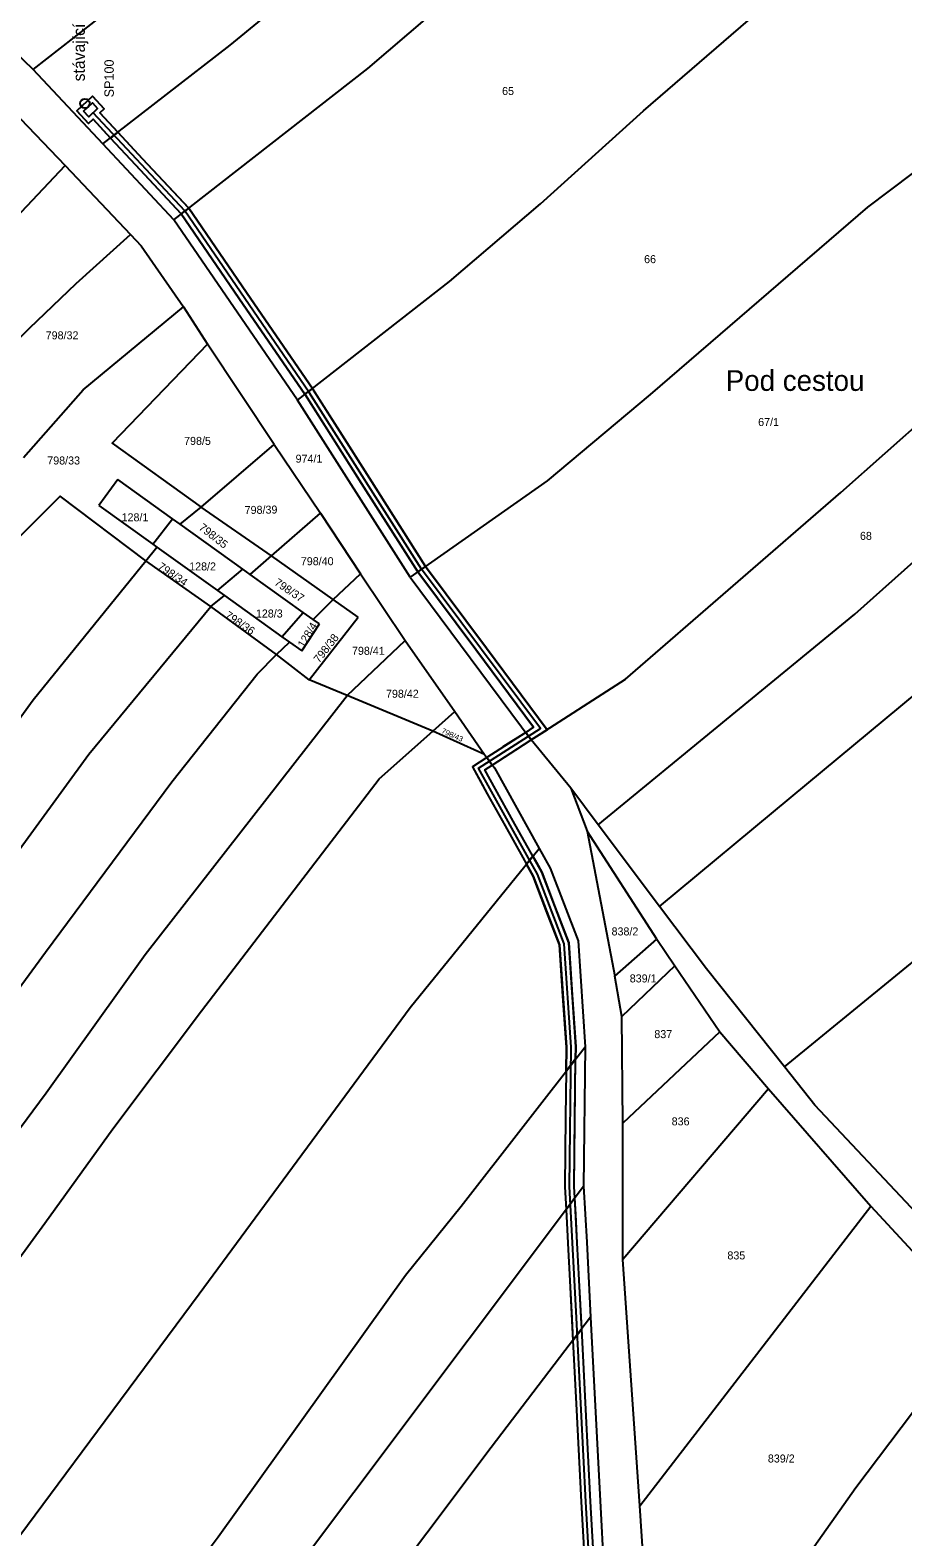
# Model space of a CAD drawing. Extents: x -7483133 to -743907, y -11317770 to -1129777.
# Drawn here: x -747694.4 to -747509.1, y -1131500 to -1131180 of the extents above; entities that cross this region are included whole.
import ezdxf

# ---------------------------------------------------------------- set-up
doc = ezdxf.new("R2010")
doc.units = 0
for name, color, linetype in [('_TRASA_vedení kabelu_CEZ', 7, 'Continuous'), ('Default', 7, 'Continuous'), ('DZ_DO_ostatní', 7, 'Continuous'), ('DZ_DO_ZPF', 7, 'Continuous'), ('Hranice parcel', 7, 'Continuous'), ('hranice VB', 7, 'Continuous'), ('Parcelní čísla', 7, 'Continuous'), ('Pop  PČ popisy', 7, 'Continuous')]:
    doc.layers.add(name, color=color, linetype=linetype)

msp = doc.modelspace()

# ---------------------------------------------------------------- linework, layer by layer
at = {"layer": '_TRASA_vedení kabelu_CEZ'}
msp.add_lwpolyline([(-747683.01, -1131197.18), (-747681.15, -1131195.45), (-747680.03, -1131196.64), (-747681.89, -1131198.38)], close=True, dxfattribs=at)
msp.add_lwpolyline([(-747575.58, -1131507.34), (-747576.38, -1131492.52), (-747578.4, -1131453.5), (-747579.22, -1131437.56), (-747579.88, -1131425.59), (-747579.54, -1131395.96), (-747581.01, -1131374.06), (-747586.67, -1131359.23), (-747588.9, -1131355.23), (-747596.45, -1131341.71), (-747599.17, -1131336.75), (-747586.05, -1131328.3), (-747611.25, -1131294.46), (-747635.1, -1131256.91), (-747661.52, -1131218.38), (-747680.96, -1131197.51)], dxfattribs=at)
at = {"layer": 'Default'}
msp.add_circle((-747682.72, -1131195.55), 1, dxfattribs=at)
msp.add_circle((-747682.72, -1131195.55), 1, dxfattribs=at)
at = {"layer": 'DZ_DO_ostatní'}
msp.add_lwpolyline([(-747587.98, -1131330.73), (-747589.17, -1131329.12), (-747597.45, -1131334.46), (-747596.27, -1131336.08)], close=True, dxfattribs=at)
at = {"layer": 'DZ_DO_ZPF'}
for points in [[(-747681.1, -1131194.04), (-747684.42, -1131197.13), (-747681.94, -1131199.79), (-747681.01, -1131198.92), (-747677.32, -1131202.89), (-747675.73, -1131201.66), (-747679.55, -1131197.56), (-747678.62, -1131196.69)], [(-747675.73, -1131201.66), (-747677.32, -1131202.89), (-747672, -1131208.6), (-747662.31, -1131219), (-747660.71, -1131217.8), (-747660.74, -1131217.75), (-747670.49, -1131207.29)], [(-747660.7, -1131217.79), (-747662.29, -1131219.03), (-747649.12, -1131238.23), (-747636.02, -1131257.33), (-747634.44, -1131256.09), (-747647.5, -1131237.05)], [(-747634.44, -1131256.09), (-747636.02, -1131257.33), (-747624, -1131276.24), (-747612.07, -1131295.03), (-747610.44, -1131293.86), (-747622.34, -1131275.12)], [(-747610.44, -1131293.86), (-747612.07, -1131295.03), (-747599.78, -1131311.53), (-747587.49, -1131328.04), (-747589.17, -1131329.12), (-747587.97, -1131330.74), (-747584.61, -1131328.56), (-747597.51, -1131311.23)], [(-747596.27, -1131336.08), (-747597.45, -1131334.46), (-747600.49, -1131336.42), (-747597.33, -1131342.19), (-747593.55, -1131348.96), (-747589.77, -1131355.72), (-747588.99, -1131357.11), (-747587.64, -1131355.44), (-747591.8, -1131347.98), (-747595.58, -1131341.22), (-747597.84, -1131337.09)], [(-747587.64, -1131355.44), (-747588.99, -1131357.11), (-747587.57, -1131359.66), (-747582, -1131374.28), (-747580.54, -1131395.99), (-747580.6, -1131401.09), (-747578.57, -1131398.49), (-747578.54, -1131395.94), (-747580.03, -1131373.84), (-747585.76, -1131358.81)], [(-747578.57, -1131398.49), (-747580.6, -1131401.09), (-747580.71, -1131410.8), (-747580.88, -1131425.61), (-747580.61, -1131430.49), (-747578.75, -1131428), (-747578.88, -1131425.56)], [(-747578.75, -1131428), (-747580.61, -1131430.49), (-747580.21, -1131437.61), (-747579.8, -1131445.58), (-747579.15, -1131458.26), (-747577.28, -1131455.8), (-747577.81, -1131445.48), (-747578.22, -1131437.51)], [(-747577.28, -1131455.8), (-747579.15, -1131458.26), (-747578.38, -1131473.06), (-747577.37, -1131492.57), (-747576.57, -1131507.4), (-747576.32, -1131512.18), (-747574.45, -1131509.68), (-747574.98, -1131499.88), (-747575.38, -1131492.47), (-747576.39, -1131472.96)]]:
    msp.add_lwpolyline(points, close=True, dxfattribs=at)
at = {"layer": 'Hranice parcel'}
for p, q in [((-747693.71, -1131188.35), (-747705.95, -1131176.64)), ((-747678.94, -1131204.15), (-747693.71, -1131188.35)), ((-747699.59, -1131195.48), (-747686.96, -1131208.76)), ((-747663.87, -1131220.26), (-747678.94, -1131204.15)), ((-747686.96, -1131208.76), (-747673.07, -1131223.37)), ((-747637.6, -1131258.56), (-747663.87, -1131220.26)), ((-747661.79, -1131238.73), (-747656.71, -1131246.65)), ((-747642.55, -1131267.96), (-747656.71, -1131246.65)), ((-747613.72, -1131296.16), (-747637.6, -1131258.56)), ((-747658.09, -1131281.3), (-747642.55, -1131267.96)), ((-747642.55, -1131267.96), (-747632.73, -1131282.6)), ((-747675.77, -1131275.42), (-747679.79, -1131280.94)), ((-747664.12, -1131283.77), (-747675.77, -1131275.42)), ((-747679.79, -1131280.94), (-747668.32, -1131289.17)), ((-747662.52, -1131284.92), (-747658.09, -1131281.3)), ((-747643.16, -1131291.66), (-747658.09, -1131281.3)), ((-747668.32, -1131289.17), (-747664.12, -1131283.77)), ((-747662.52, -1131284.92), (-747664.12, -1131283.77)), ((-747649.2, -1131294.46), (-747662.52, -1131284.92)), ((-747643.16, -1131291.66), (-747632.73, -1131282.6)), ((-747632.73, -1131282.6), (-747624.26, -1131295.45)), ((-747669.82, -1131292.66), (-747667.48, -1131289.77)), ((-747668.32, -1131289.17), (-747667.48, -1131289.77)), ((-747667.48, -1131289.77), (-747654.61, -1131299)), ((-747656, -1131302.39), (-747669.82, -1131292.66)), ((-747654.61, -1131299), (-747649.2, -1131294.46)), ((-747647.65, -1131295.57), (-747649.2, -1131294.46)), ((-747647.65, -1131295.57), (-747643.16, -1131291.66)), ((-747630.05, -1131300.93), (-747643.16, -1131291.66)), ((-747636.4, -1131303.63), (-747647.65, -1131295.57)), ((-747630.05, -1131300.93), (-747624.26, -1131295.45)), ((-747624.26, -1131295.45), (-747614.76, -1131309.6)), ((-747613.72, -1131296.16), (-747587.97, -1131330.74)), ((-747656, -1131302.39), (-747653.1, -1131300.08)), ((-747654.61, -1131299), (-747653.1, -1131300.08)), ((-747653.1, -1131300.08), (-747640.91, -1131308.82)), ((-747634.28, -1131305.15), (-747630.05, -1131300.93)), ((-747624.72, -1131304.69), (-747630.05, -1131300.93)), ((-747642.09, -1131312.59), (-747656, -1131302.39)), ((-747640.91, -1131308.82), (-747636.4, -1131303.63)), ((-747634.28, -1131305.15), (-747636.4, -1131303.63)), ((-747636.7, -1131311.84), (-747632.97, -1131306.09)), ((-747635.14, -1131317.96), (-747624.72, -1131304.69)), ((-747632.97, -1131306.09), (-747634.28, -1131305.15)), ((-747642.09, -1131312.59), (-747639.3, -1131309.98)), ((-747640.91, -1131308.82), (-747639.3, -1131309.98)), ((-747639.3, -1131309.98), (-747636.7, -1131311.84)), ((-747627.04, -1131321.32), (-747614.76, -1131309.6)), ((-747614.76, -1131309.6), (-747604.21, -1131324.68)), ((-747635.14, -1131317.96), (-747642.09, -1131312.59)), ((-747627.04, -1131321.32), (-747635.14, -1131317.96)), ((-747608.88, -1131328.87), (-747627.04, -1131321.32)), ((-747608.88, -1131328.87), (-747604.21, -1131324.68)), ((-747604.21, -1131324.68), (-747597.93, -1131333.8)), ((-747597.93, -1131333.8), (-747608.88, -1131328.87)), ((-747579.59, -1131341), (-747587.97, -1131330.74)), ((-747573.75, -1131348.78), (-747579.59, -1131341)), ((-747579.59, -1131341), (-747576.14, -1131350.08)), ((-747560.74, -1131366.12), (-747573.75, -1131348.78)), ((-747576.14, -1131350.08), (-747570.26, -1131380.88)), ((-747561.31, -1131373.03), (-747576.14, -1131350.08)), ((-747570.26, -1131380.88), (-747561.31, -1131373.03)), ((-747561.31, -1131373.03), (-747557.5, -1131378.68)), ((-747568.77, -1131389.44), (-747570.26, -1131380.88)), ((-747557.5, -1131378.68), (-747568.77, -1131389.44)), ((-747557.5, -1131378.68), (-747547.95, -1131392.74)), ((-747568.57, -1131412.15), (-747568.77, -1131389.44)), ((-747547.95, -1131392.74), (-747568.57, -1131412.15)), ((-747547.95, -1131392.74), (-747537.66, -1131404.8)), ((-747576.54, -1131395.88), (-747576.88, -1131425.52)), ((-747537.66, -1131404.8), (-747568.52, -1131441.05)), ((-747537.66, -1131404.8), (-747515.93, -1131429.75)), ((-747568.52, -1131441.05), (-747568.57, -1131412.15)), ((-747564.97, -1131493.37), (-747515.93, -1131429.75)), ((-747515.93, -1131429.75), (-747492.83, -1131454.72)), ((-747564.97, -1131493.37), (-747568.52, -1131441.05))]:
    msp.add_line(p, q, dxfattribs=at)
for points in [[(-747693.71, -1131188.35), (-747673.39, -1131172.41), (-747656.27, -1131158.12), (-747617.7, -1131124.35), (-747583.1, -1131094.79)], [(-747678.94, -1131204.15), (-747651.91, -1131183.16), (-747620.97, -1131157.74), (-747567.13, -1131110.4)], [(-747663.87, -1131220.26), (-747622.68, -1131188.16), (-747577.82, -1131149.69), (-747551.23, -1131125.94)], [(-747637.6, -1131258.56), (-747605.36, -1131233.4), (-747586.04, -1131216.89), (-747564.17, -1131197.09), (-747518.15, -1131157.34)], [(-747478.68, -1131189), (-747516.61, -1131217.55), (-747562.75, -1131257.36), (-747584.62, -1131275.69), (-747613.72, -1131296.16)], [(-747719.59, -1131243.31), (-747710.17, -1131233.27), (-747686.96, -1131208.76)], [(-747587.97, -1131330.74), (-747567.99, -1131317.8), (-747522.26, -1131278.21), (-747503.48, -1131261.46), (-747452.5, -1131218.84)], [(-747705.1, -1131253.98), (-747694.48, -1131243.3), (-747684.57, -1131233.76), (-747673.07, -1131223.37)], [(-747673.07, -1131223.37), (-747670.79, -1131225.76), (-747661.79, -1131238.73)], [(-747695.74, -1131270.78), (-747683.08, -1131256.39), (-747661.79, -1131238.73)], [(-747573.75, -1131348.78), (-747519.29, -1131304), (-747475.75, -1131265.13), (-747451.48, -1131246.17), (-747439.12, -1131238.12)], [(-747656.71, -1131246.65), (-747676.97, -1131267.67), (-747658.09, -1131281.3)], [(-747560.74, -1131366.12), (-747532.83, -1131342.86), (-747438.82, -1131264.87), (-747425.11, -1131256.95)], [(-747669.82, -1131292.66), (-747687.96, -1131278.99), (-747702.43, -1131293.35), (-747710.63, -1131287.46)], [(-747915.42, -1131619.45), (-747873.23, -1131566.86), (-747843.82, -1131525.97), (-747806.53, -1131475.44), (-747778.43, -1131437.61), (-747729.49, -1131371.5), (-747693.71, -1131322.2), (-747669.82, -1131292.66)], [(-747534.26, -1131400.17), (-747480.38, -1131356.14), (-747430.3, -1131312.29), (-747401.97, -1131292.55)], [(-747895.76, -1131621.42), (-747861.58, -1131578.6), (-747835.67, -1131543.4), (-747806.42, -1131503.18), (-747795.07, -1131488.14), (-747755.24, -1131433.32), (-747715.49, -1131379.82), (-747681.87, -1131333.76), (-747656, -1131302.39)], [(-747879, -1131625.66), (-747851.66, -1131591.69), (-747829.65, -1131563.42), (-747808.64, -1131535.34), (-747757.65, -1131465.52), (-747713.97, -1131406.96), (-747691.09, -1131375.78), (-747664.28, -1131339.63), (-747646.2, -1131316.75), (-747642.09, -1131312.59)], [(-747860.06, -1131629.88), (-747832.75, -1131596.26), (-747816.97, -1131575.83), (-747776.82, -1131523.47), (-747762.78, -1131503.59), (-747734.31, -1131465.05), (-747710.2, -1131431.58), (-747690.98, -1131405.7), (-747669.96, -1131376.28), (-747627.04, -1131321.32)], [(-747842.01, -1131634.16), (-747811.79, -1131593.14), (-747801.87, -1131584.09), (-747752.07, -1131516.87), (-747707.12, -1131455.02), (-747691.23, -1131433.37), (-747676.82, -1131413.33), (-747658, -1131388.25), (-747620.26, -1131339), (-747608.88, -1131328.87)], [(-747597.93, -1131333.8), (-747595.82, -1131336.69), (-747586.28, -1131353.77)], [(-747806.67, -1131645.86), (-747760.08, -1131583.56), (-747741.05, -1131557.9), (-747711.67, -1131520.04), (-747658.45, -1131448.35), (-747613.7, -1131387.55), (-747586.28, -1131353.77)], [(-747586.28, -1131353.77), (-747583.94, -1131357.96), (-747578.05, -1131373.41), (-747576.54, -1131395.88)], [(-747534.26, -1131400.17), (-747550.8, -1131379.36), (-747560.74, -1131366.12)], [(-747772.35, -1131654.05), (-747742.69, -1131616.2), (-747708.15, -1131571.7), (-747696.05, -1131555.49), (-747654.43, -1131499.96), (-747614.66, -1131444.39), (-747602.9, -1131429.72), (-747576.54, -1131395.88)], [(-747506.23, -1131431.25), (-747527.79, -1131408.31), (-747534.26, -1131400.17)], [(-747751.97, -1131658.69), (-747725.51, -1131622.95), (-747709.1, -1131600.51), (-747691.54, -1131577.63), (-747669.23, -1131548.64), (-747625.65, -1131490.48), (-747576.88, -1131425.52)], [(-747576.88, -1131425.52), (-747576.22, -1131437.4), (-747575.4, -1131453.35)], [(-747575.4, -1131453.35), (-747596.53, -1131480.99), (-747637.49, -1131535.62), (-747681.61, -1131594.97), (-747707.2, -1131626.86), (-747733.77, -1131662.83)], [(-747575.4, -1131453.35), (-747573.38, -1131492.36), (-747572.58, -1131507.18)], [(-747559.72, -1131546.32), (-747549.84, -1131533.09), (-747519.12, -1131489.53), (-747492.83, -1131454.72)], [(-747559.72, -1131546.32), (-747562.72, -1131526.64), (-747564.97, -1131493.37)]]:
    msp.add_lwpolyline(points, dxfattribs=at)
at = {"layer": 'hranice VB'}
for p, q in [((-747672, -1131208.6), (-747677.3, -1131202.91)), ((-747662.29, -1131219.03), (-747672, -1131208.6)), ((-747660.71, -1131217.8), (-747662.29, -1131219.03)), ((-747660.71, -1131217.8), (-747647.5, -1131237.05)), ((-747649.12, -1131238.23), (-747662.29, -1131219.03)), ((-747647.5, -1131237.05), (-747634.44, -1131256.09)), ((-747636.02, -1131257.33), (-747649.12, -1131238.23)), ((-747634.44, -1131256.09), (-747636.02, -1131257.33)), ((-747622.34, -1131275.12), (-747610.44, -1131293.86)), ((-747612.08, -1131295.01), (-747624, -1131276.24)), ((-747610.44, -1131293.86), (-747612.08, -1131295.01)), ((-747587.49, -1131328.04), (-747599.78, -1131311.53)), ((-747597.51, -1131311.23), (-747584.61, -1131328.56)), ((-747589.17, -1131329.12), (-747593.99, -1131332.23)), ((-747589.17, -1131329.12), (-747587.49, -1131328.04)), ((-747587.98, -1131330.73), (-747589.17, -1131329.12)), ((-747584.61, -1131328.56), (-747587.98, -1131330.73)), ((-747593.99, -1131332.23), (-747597.45, -1131334.46)), ((-747596.27, -1131336.08), (-747591.23, -1131332.83)), ((-747591.23, -1131332.83), (-747587.98, -1131330.73)), ((-747597.45, -1131334.46), (-747600.49, -1131336.42)), ((-747597.84, -1131337.09), (-747596.27, -1131336.08)), ((-747597.45, -1131334.46), (-747596.27, -1131336.08)), ((-747600.49, -1131336.42), (-747598.91, -1131339.3)), ((-747598.91, -1131339.3), (-747597.33, -1131342.19)), ((-747595.58, -1131341.22), (-747597.84, -1131337.09)), ((-747597.33, -1131342.19), (-747593.55, -1131348.96)), ((-747591.8, -1131347.98), (-747595.58, -1131341.22)), ((-747593.55, -1131348.96), (-747589.77, -1131355.72)), ((-747587.64, -1131355.44), (-747591.8, -1131347.98)), ((-747588.99, -1131357.11), (-747587.64, -1131355.44)), ((-747587.64, -1131355.44), (-747586.89, -1131356.78)), ((-747589.77, -1131355.72), (-747588.99, -1131357.11)), ((-747587.57, -1131359.66), (-747588.99, -1131357.11)), ((-747586.89, -1131356.78), (-747585.76, -1131358.81)), ((-747584.79, -1131366.97), (-747587.57, -1131359.66)), ((-747585.76, -1131358.81), (-747582.89, -1131366.33)), ((-747582, -1131374.28), (-747584.79, -1131366.97)), ((-747582.89, -1131366.33), (-747580.03, -1131373.84)), ((-747581.27, -1131385.13), (-747582, -1131374.28)), ((-747580.03, -1131373.84), (-747579.28, -1131384.89)), ((-747580.54, -1131395.99), (-747581.27, -1131385.13)), ((-747579.28, -1131384.89), (-747578.54, -1131395.94)), ((-747580.6, -1131401.09), (-747580.54, -1131395.99)), ((-747578.54, -1131395.94), (-747578.57, -1131398.49)), ((-747578.57, -1131398.49), (-747580.6, -1131401.09)), ((-747578.71, -1131410.75), (-747578.57, -1131398.49)), ((-747580.6, -1131401.09), (-747580.71, -1131410.8)), ((-747580.71, -1131410.8), (-747580.88, -1131425.61)), ((-747578.88, -1131425.56), (-747578.71, -1131410.75)), ((-747580.88, -1131425.61), (-747580.61, -1131430.49)), ((-747578.75, -1131428), (-747578.88, -1131425.56)), ((-747580.61, -1131430.49), (-747578.75, -1131428)), ((-747578.55, -1131431.54), (-747578.75, -1131428)), ((-747580.61, -1131430.49), (-747580.21, -1131437.61)), ((-747578.22, -1131437.51), (-747578.55, -1131431.54)), ((-747580.21, -1131437.61), (-747579.8, -1131445.58)), ((-747577.81, -1131445.48), (-747578.22, -1131437.51)), ((-747579.8, -1131445.58), (-747579.39, -1131453.56)), ((-747577.4, -1131453.45), (-747577.81, -1131445.48)), ((-747579.39, -1131453.56), (-747579.15, -1131458.26)), ((-747577.28, -1131455.8), (-747577.4, -1131453.45)), ((-747579.15, -1131458.26), (-747577.28, -1131455.8)), ((-747576.39, -1131472.96), (-747577.28, -1131455.8)), ((-747579.15, -1131458.26), (-747578.38, -1131473.06)), ((-747578.38, -1131473.06), (-747577.37, -1131492.57)), ((-747575.38, -1131492.47), (-747576.39, -1131472.96)), ((-747577.37, -1131492.57), (-747576.97, -1131499.98)), ((-747574.98, -1131499.88), (-747575.38, -1131492.47)), ((-747574.58, -1131507.29), (-747574.98, -1131499.88))]:
    msp.add_line(p, q, dxfattribs=at)
for points in [[(-747677.32, -1131202.89), (-747681.01, -1131198.92), (-747681.94, -1131199.79), (-747684.42, -1131197.13), (-747681.1, -1131194.04), (-747678.62, -1131196.69), (-747679.55, -1131197.56), (-747675.73, -1131201.66), (-747677.3, -1131202.91)], [(-747675.73, -1131201.66), (-747670.49, -1131207.29), (-747662.78, -1131215.56), (-747660.74, -1131217.75), (-747660.71, -1131217.8)], [(-747634.44, -1131256.09), (-747634.26, -1131256.36), (-747628.64, -1131265.21), (-747622.34, -1131275.12)], [(-747624, -1131276.24), (-747635.93, -1131257.46), (-747636.02, -1131257.33)], [(-747610.44, -1131293.86), (-747610.42, -1131293.89), (-747597.51, -1131311.23)], [(-747599.78, -1131311.53), (-747612.07, -1131295.03), (-747612.08, -1131295.01)]]:
    msp.add_lwpolyline(points, dxfattribs=at)

# ---------------------------------------------------------------- texts
at = {"layer": '_TRASA_vedení kabelu_CEZ'}
for s, height, p in [('stávající sloup na parcele 64/1', 2.5, (-747682.75, -1131190.86)), ('SP100', 2, (-747676.6, -1131194.25))]:
    msp.add_text(s, height=height, rotation=90, dxfattribs=at).set_placement(p)
at = {"layer": 'Parcelní čísla'}
for s, p in [('65', (-747594.18, -1131193.76)), ('66', (-747564.03, -1131229.47)), ('798/32', (-747691.06, -1131245.65)), ('67/1', (-747539.82, -1131264.06)), ('798/5', (-747661.68, -1131268.07)), ('798/33', (-747690.73, -1131272.23)), ('974/1', (-747638.01, -1131271.84)), ('128/1', (-747674.95, -1131284.3)), ('68', (-747518.21, -1131288.24)), ('128/2', (-747660.6, -1131294.73)), ('798/40', (-747636.9, -1131293.62)), ('128/3', (-747646.44, -1131304.73)), ('798/41', (-747626.04, -1131312.65)), ('798/42', (-747618.82, -1131321.77)), ('838/2', (-747570.94, -1131372.25)), ('839/1', (-747567.08, -1131382.23)), ('837', (-747561.86, -1131394.06)), ('836', (-747558.18, -1131412.59)), ('835', (-747546.35, -1131441.06)), ('839/2', (-747537.76, -1131484.19))]:
    msp.add_text(s, height=1.7, dxfattribs=at).set_placement(p)
for s, height, rotation, p in [('798/39', 1.7, 1, (-747648.81, -1131282.76)), ('798/35', 1.7, 322, (-747658.7, -1131285.91)), ('798/34', 1.7, 326, (-747667.43, -1131294.3)), ('798/37', 1.7, 326, (-747642.68, -1131297.68)), ('798/36', 1.7, 326, (-747653.17, -1131304.65)), ('128/4', 1.7, 59, (-747636.25, -1131311.3)), ('798/38', 1.7, 52, (-747633.01, -1131314.51)), ('798/43', 1.14, 336, (-747607.16, -1131329.21))]:
    msp.add_text(s, height=height, rotation=rotation, dxfattribs=at).set_placement(p)
at = {"layer": 'Pop  PČ popisy'}
msp.add_text('Pod cestou', height=4.4, dxfattribs=at).set_placement((-747546.7, -1131256.6))

doc.saveas('drawing.dxf')
